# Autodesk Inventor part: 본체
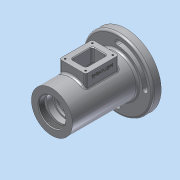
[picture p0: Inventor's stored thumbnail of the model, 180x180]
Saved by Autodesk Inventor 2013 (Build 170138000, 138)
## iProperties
Created: 2017-05
Part Number: 본체
Material: 알루미늄 6061
Document SubType Name: Modeling
Designer: dgall
Density: 1 g/cm^3
Author: dgall
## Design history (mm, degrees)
revolve "회전1" stored, may be unused: angle "d8" = 90 deg
revolve "회전2" stored, may be unused: angle "d37" = 90 deg
node "작업 평면1"
sketch "스케치2"
  geometry: L1 (-81, -20)-(-31, -20); L2 (-31, -20)-(-31, 20); L3 (-31, 20)-(-81, 20); L4 (-81, 20)-(-81, -20); 3 further points
  constraints: 8 end point, 2 midpoint, 2 parallel, 1 horizontal, 1 horizontal alignment, 1 perpendicular
  dimensions: "d39" = 50 distance of L3.end L2.end; "d40" = 40 distance of L2.end L1.end; "d41" = 56 horizontal distance of point (0, 0) point (-56, -20)
extrude "돌출1" join sketch "스케치2" stored distance "d42" = 10; taper "d43" = 0 deg
sketch "스케치3"
  geometry: L1 (81, 20)-(31, 20) reference; L2 (40, -11)-(72, -11); L3 (72, -11)-(72, 11); L4 (72, 11)-(40, 11); L5 (40, 11)-(40, -11); 4 further points
  constraints: 8 end point, 3 midpoint, 2 parallel, 1 horizontal, 1 horizontal alignment, 1 perpendicular, 1 vertical alignment
  dimensions: "d49" = 32 distance of L4.end L3.end; "d50" = 22 distance of L3.end L2.end
extrude "돌출2" cut sketch "스케치3" distance "d51" = 50; taper "d52" = 0 deg
fillet "모깎기1" dims "d53" = 3
fillet "모깎기2" dims "d54" = 3
sketch "스케치4"
  geometry: L1 (43, 11)-(69, 11) reference; 4 further points
  constraints: 2 midpoint, 1 coincident
  dimensions: "d55" = 15.5 vertical distance of point (0, 0) point (35.5, 15.5); "d56" = 20.5 horizontal distance of point (35.5, 15.5) point (56, 11)
hole "구멍1" sketch "스케치4" at (35.5, 15.5) diameter "d57" = 2.621; stored, may be unused: countersink angle "d61" = 90 deg, drill point angle "d63" = 118 deg; dims "d58" = 6, "d59" = 4, "d60" = 2, "d62" = 8
sketch "스케치6"
  geometry: C1 r 31 at (0, 0) reference; C2 r 53 at (0, 0) reference; A1 r 37.5 centre (0, 0) between (0, 37.5) and (-37.5, 0); A2 r 45.5 centre (0, 0) between (0, 45.5) and (-45.5, 0); A3 r 4 centre (-41.5, 0) between (-45.5, 0) and (-37.5, 0); A4 r 4 centre (0, 41.5) between (0, 37.5) and (0, 45.5); A5 r 37.5 centre (0, 0) between (0, -37.5) and (37.5, 0); A6 r 45.5 centre (0, 0) between (0, -45.5) and (45.5, 0); A7 r 4 centre (0, -41.5) between (0, -37.5) and (0, -45.5); A8 r 4 centre (41.5, 0) between (45.5, 0) and (37.5, 0)
  constraints: 16 point on circle, 8 centre point, 8 tangent, 4 coincident, 2 concentric, 2 horizontal alignment, 2 vertical alignment
  dimensions: "d70" = 37.5 radius of A1; "d73" = 45.5 radius of A2
extrude "돌출3" cut sketch "스케치6" stored distance "d74" = 10; taper "d75" = 0 deg
fillet "모깎기3" dims "d76" = 3
hole "구멍2" diameter "d80" = 40.376; stored, may be unused: countersink angle "d84" = 90 deg, drill point angle "d86" = 0 deg; dims "d78" = 10, "d79" = 10, "d81" = 6, "d82" = 4, "d83" = 2, "d85" = 9
chamfer "모따기1" distance "d87" = 1; stored, may be unused: second distance "d88" = 2, angle "d89" = 45 deg
fillet "모깎기4" dims "d90" = 3
sketch "스케치7"
  geometry: L1 (0, 0)-(44, 0) reference; L2 (-34, -75)-(-34, -13) reference; 2 further points
  constraints: 1 other
  dimensions: "d91" = 56 distance from line of L2 point (22, -8); "d92" = 8 distance from line of L1 point (22, -8)
feature "엠보싱1" sketch "스케치7" dims "d93" = 0.5, "d94" = 0
chamfer "모따기2" distance "d97" = 1; stored, may be unused: second distance "d98" = 2, angle "d99" = 45 deg
node "솔리드1"
sketch "스케치1"
  geometry: L1 (0, 0)-(115, 0); L2 (0, 0)-(0, 31); L3 (0, 31)-(99, 31); L4 (99, 31)-(99, 53); L5 (99, 53)-(112, 53); L6 (112, 53)-(112, 31); L7 (112, 31)-(115, 31); L8 (115, 31)-(115, 0); L9 (9, 21)-(9, 24); L10 (9, 24)-(12, 24); L11 (12, 24)-(12, 20); L12 (12, 20)-(21, 20); L13 (21, 20)-(21, 17.5); L14 (21, 17.5)-(24.25, 17.5); L15 (24.25, 17.5)-(24.25, 18.5); L16 (24.25, 18.5)-(26, 18.5); L17 (26, 18.5)-(26, 17.5); L18 (26, 17.5)-(36, 17.5); L19 (37, 18.5)-(37, 23); L20 (40, 26)-(72, 26); L21 (75, 23)-(75, 18.5); L22 (76, 17.5)-(85.7, 17.5); L23 (86, 17.2)-(86, 16.5); L24 (86, 16.5)-(88, 16.5); L25 (91, 13.5)-(91, 10); L26 (91, 10)-(93.7, 10); L27 (93.7, 10)-(93.7, 12.2); L28 (94, 12.5)-(100.3, 12.5); L29 (100.3, 12.5)-(101, 12.904); L30 (101, 12.904)-(101, 14.022); L31 (102.818, 16.779)-(115, 22); L32 (37, 18.5)-(36, 17.5); L33 (75, 18.5)-(76, 17.5); L34 (9, 21)-(9, 0); A1 r 0.3 centre (94, 12.2) between (94, 12.5) and (93.7, 12.2); A2 r 0.3 centre (85.7, 17.2) between (86, 17.2) and (85.7, 17.5); A3 r 3 centre (40, 23) between (40, 26) and (37, 23); A4 r 3 centre (72, 23) between (75, 23) and (72, 26); A5 r 3 centre (88, 13.5) between (91, 13.5) and (88, 16.5); A6 r 3 centre (104, 14.022) between (102.818, 16.779) and (101, 14.022); 8 further points
  constraints: 68 end point, 18 point on line, 13 parallel, 12 point on circle, 12 tangent, 8 perpendicular, 6 centre point, 3 equal radius, 3 horizontal alignment, 2 collinear, 2 horizontal, 2 vertical
  dimensions: "d0" = 115 distance of L1.start L1.end; "d1" = 62 diameter of L3 L1; "d3" = 106 diameter of L5 L1; "d6" = 3 distance of L6.end L7.end; "d7" = 13 distance of L4.end L5.end; "d10" = 48 diameter of L10 L1; "d11" = 40 diameter of L12 L1; "d13" = 35 diameter of L14 L1; "d14" = 3 distance of L9.end L10.end; "d16" = 21 distance between parallel lines of L2 L13; "d18" = 1.75 distance of L15.end L16.end; "d19" = 37 diameter of L16 L1; "d20" = 11 distance of L17.end point (37, 17.5); "d21" = 52 diameter of L20 L1; "d22" = 11 distance of point (75, 17.5) point (86, 17.5); "d23" = 33 diameter of L24 L1; "d24" = 20 diameter of L26 L1; "d25" = 5 distance of L23.end point (91, 16.5); "d26" = 2.7 distance of L25.end L26.end; "d27" = 25 diameter of L28 L1; "d29" = 0.7 horizontal distance of L28.end L29.end; "d30" = 30 deg angle of L28 L29; "d31" = 32 diameter of point (101, 16) L1; "d33" = 44 diameter of L31.end L1; "d34" = 14 horizontal distance of point (101, 16) L31.end; "d35" = 0.3 radius of A1; "d36" = 0.3 radius of A2; "d44" = 3 radius of A3; "d45" = 1 distance of L19.start point (37, 17.5); "d46" = 1 distance of L18.end point (37, 17.5) (= d45); "d47" = 1 distance of L21.end point (75, 17.5) (= d45); "d48" = 1 distance of L22.start point (75, 17.5) (= d47); "d77" = 12 distance between parallel lines of L2 L11; "d95" = 38 distance between parallel lines of L21 L19; "d96" = 26 distance from line of L2 L17.end
pattern_linear "직사각형 패턴1" dims "d66" = 41, "d69" = 31
other parameters: "d38" = 44
